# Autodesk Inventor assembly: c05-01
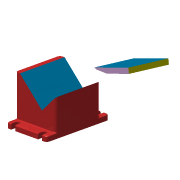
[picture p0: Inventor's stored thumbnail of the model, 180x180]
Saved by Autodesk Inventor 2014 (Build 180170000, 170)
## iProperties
Created: 2010-11
Part Number: c05-01
Document SubType Name: Assembly
Designer: Thom Tremblay
Author: Thom Tremblay
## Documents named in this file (3)
- C:\Inventor 2014 Essentials\Assemblies\Chapter 05\c05-01.iam
- C:\Inventor 2014 Essentials\Parts\Chapter 05\c05-01.ipt
- C:\Inventor 2014 Essentials\Parts\Chapter 05\c05-02.ipt
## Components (2 placed, 2 different names)
1. c05-01:1
2. c05-02:1
